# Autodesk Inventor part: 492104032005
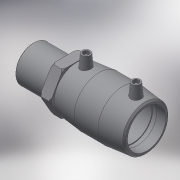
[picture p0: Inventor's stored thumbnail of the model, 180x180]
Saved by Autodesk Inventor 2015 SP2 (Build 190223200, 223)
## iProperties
Created: 2017-06
Part Number: 492104032005
Material: Generic
Description: PLASSON Male Transition Coupler 32 x 1/2"
Document SubType Name: Modeling
Designer: KIM
Mass: 93.7584 g
Surface Area: 278.651 cm^2
Volume: 93.7584 cm^3
Density: 1 g/cm^3
Appearance: Default
Author: KIM
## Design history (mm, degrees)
derived "492104.ipt"
feature "Solid1::492104.ipt"
tag "TaggingFeature1"
body "Solid1"
other parameters: "d0" = 81, "d1" = 32, "d2" = 44, "d3" = 39, "d4" = 27, "d5" = 39.6, "d6" = 30.4, "d7" = 32, "d8" = 168 deg, "d10" = 15.6, "d11" = 5.2, "d29" = 42, "d30" = 14, "d31" = 28.35, "d34" = 5 deg, "d41" = 4, "d42" = 14, "d43" = 0, "d48" = 3, "d49" = 0, "d57" = 14, "d58" = 20.955, "d59" = 16.764, "d60" = 26.1, "d61" = 44, "d62" = 0.4191, "d65" = 1.32, "d70" = 0.1, "d71" = 29, "d72" = 7.25, "d73" = 15.6, "d75" = 0, "d_" = 32, "L_1" = 39, "D_1" = 44, "A_" = 42, "d_2" = 12, "L_2" = 29, "D_" = 14, "R_" = 20.955
